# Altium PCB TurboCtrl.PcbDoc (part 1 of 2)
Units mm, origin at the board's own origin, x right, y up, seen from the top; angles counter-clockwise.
Board outline 40.25 x 40.25 mm, 4 copper layers (Top Layer, GND, SIGNAL, Bottom Layer), stack 1.571 mm thick; 111 components, 99 nets, 426 pads, 163 vias.
Unrouted connection lines stored in the file: 47.
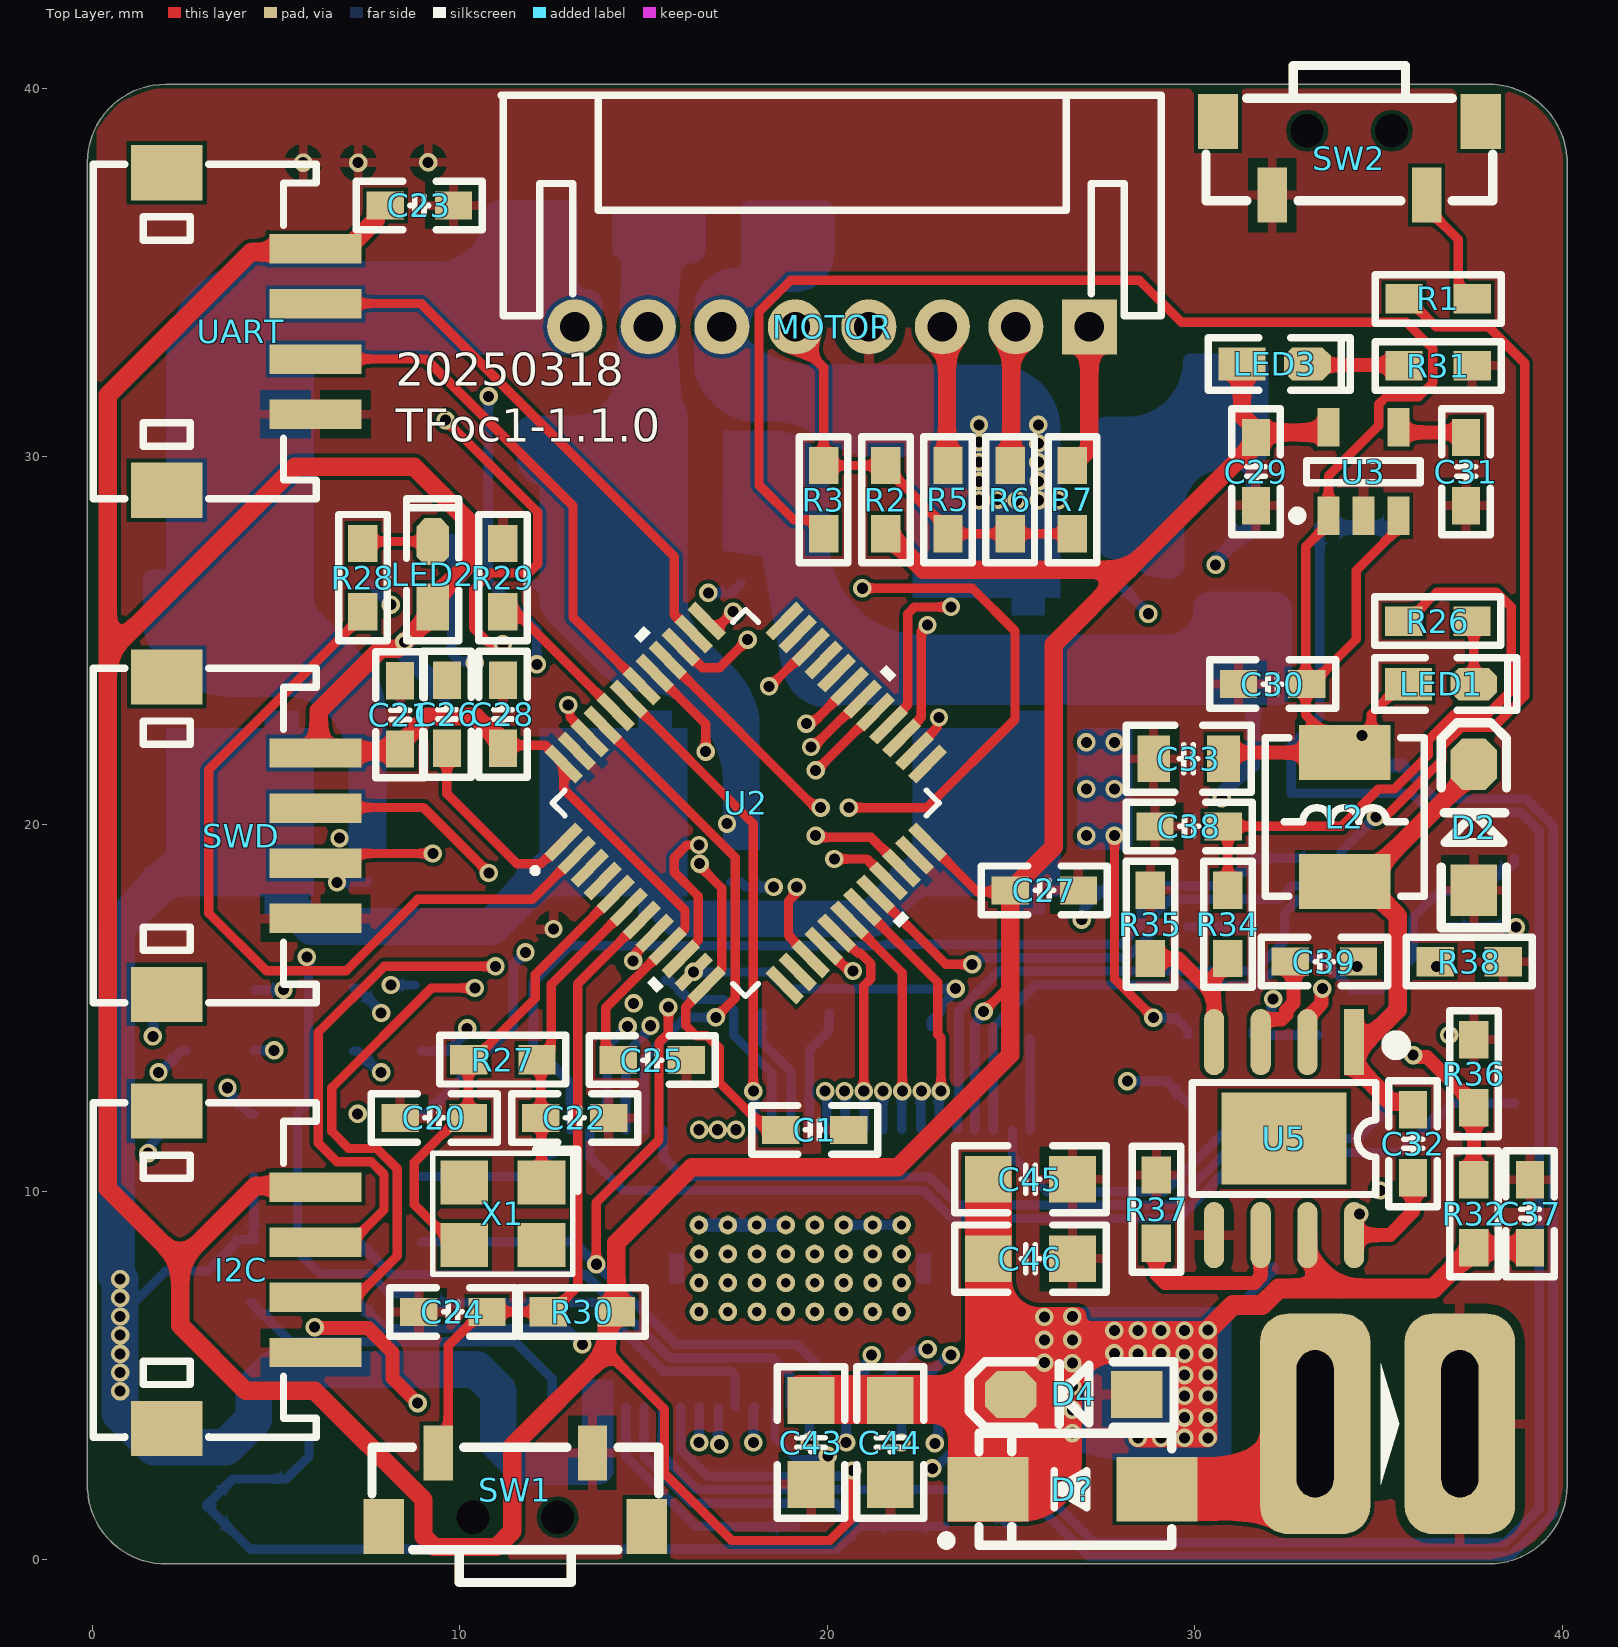
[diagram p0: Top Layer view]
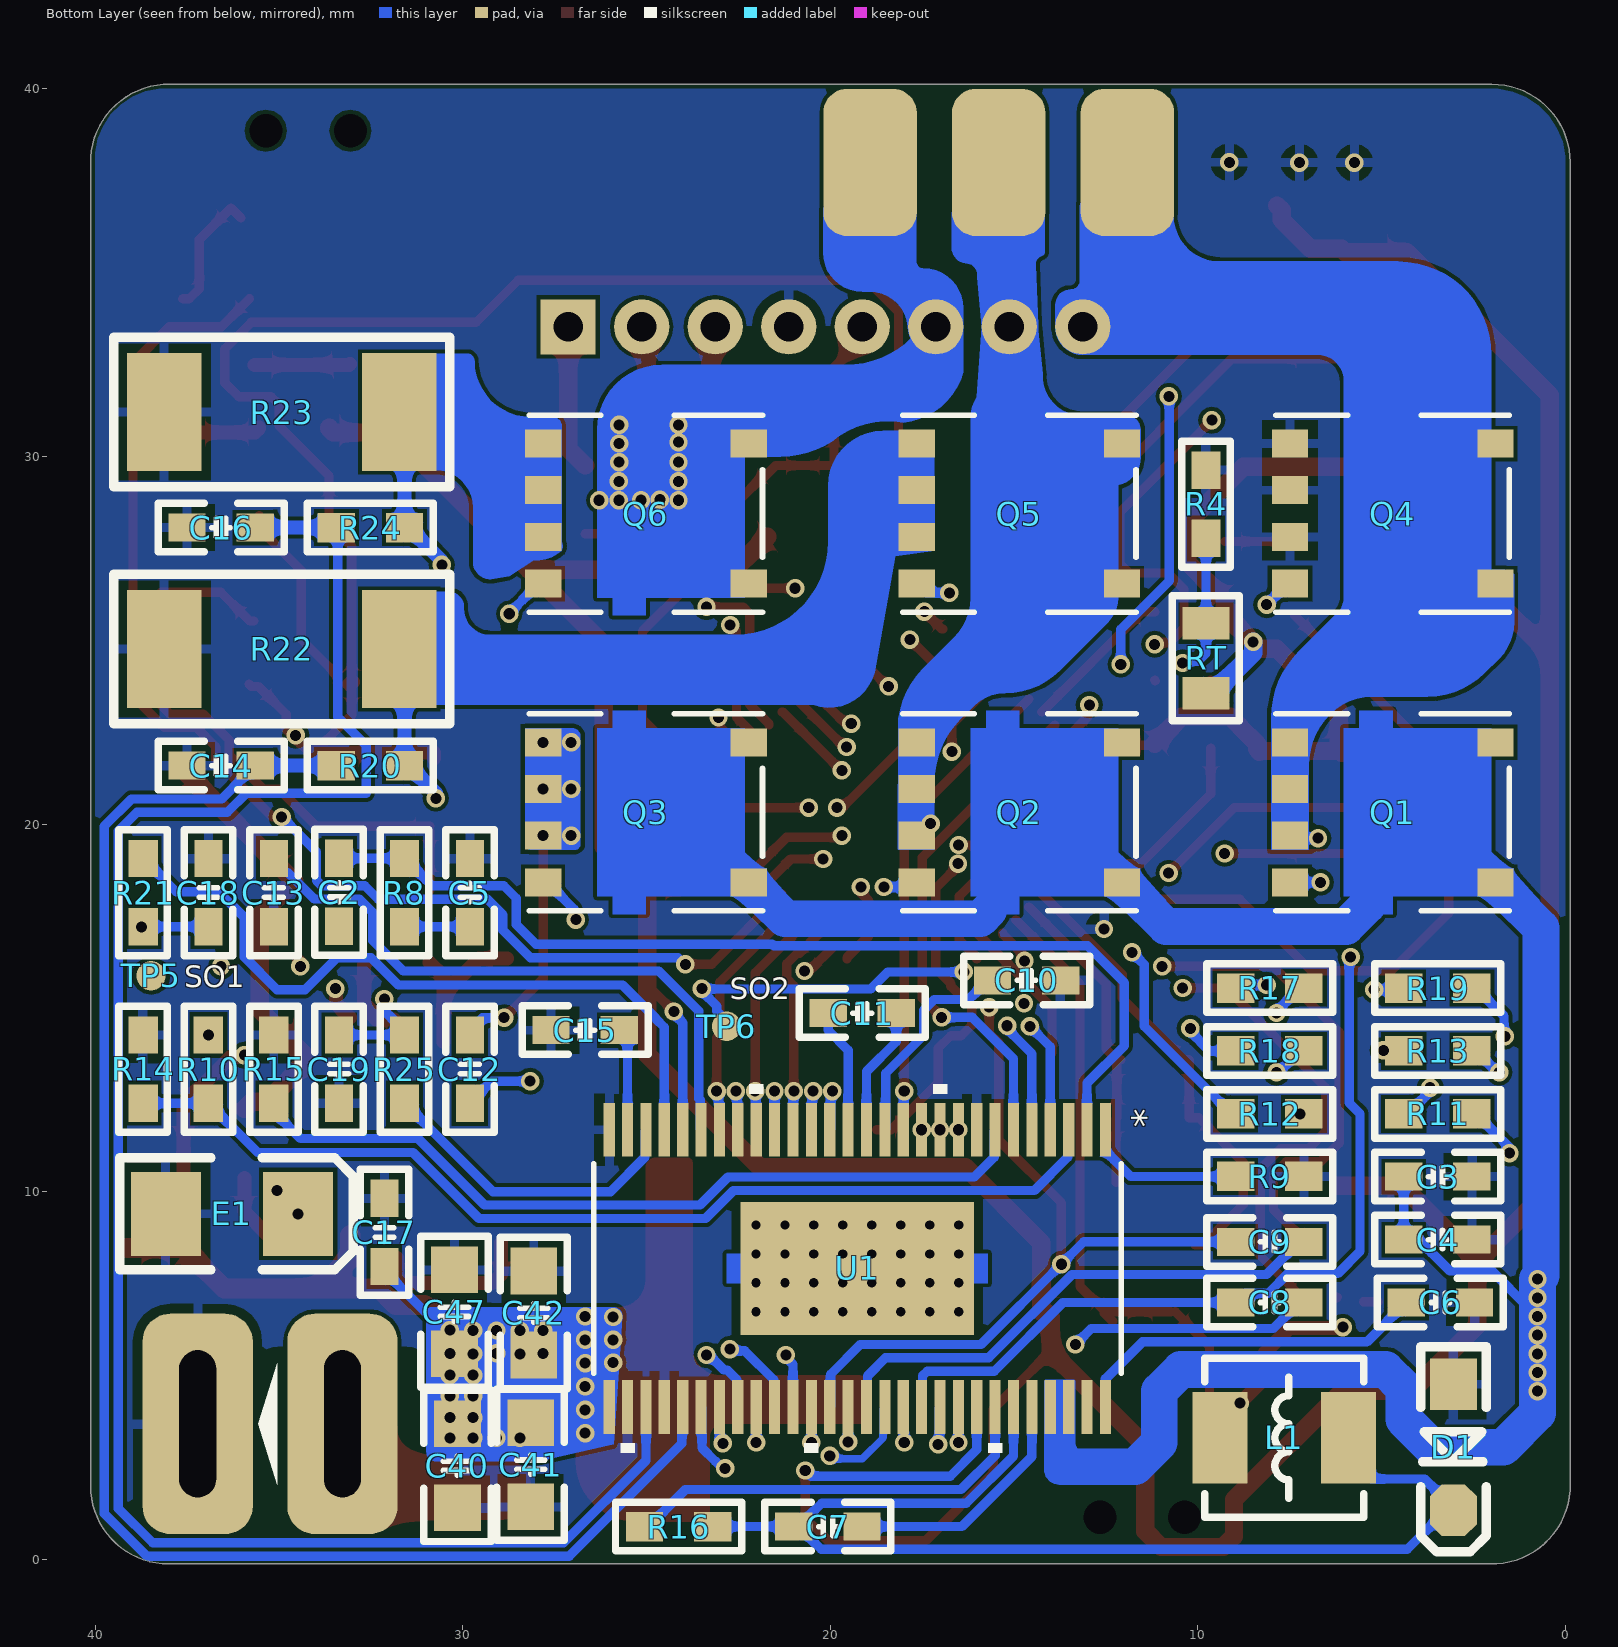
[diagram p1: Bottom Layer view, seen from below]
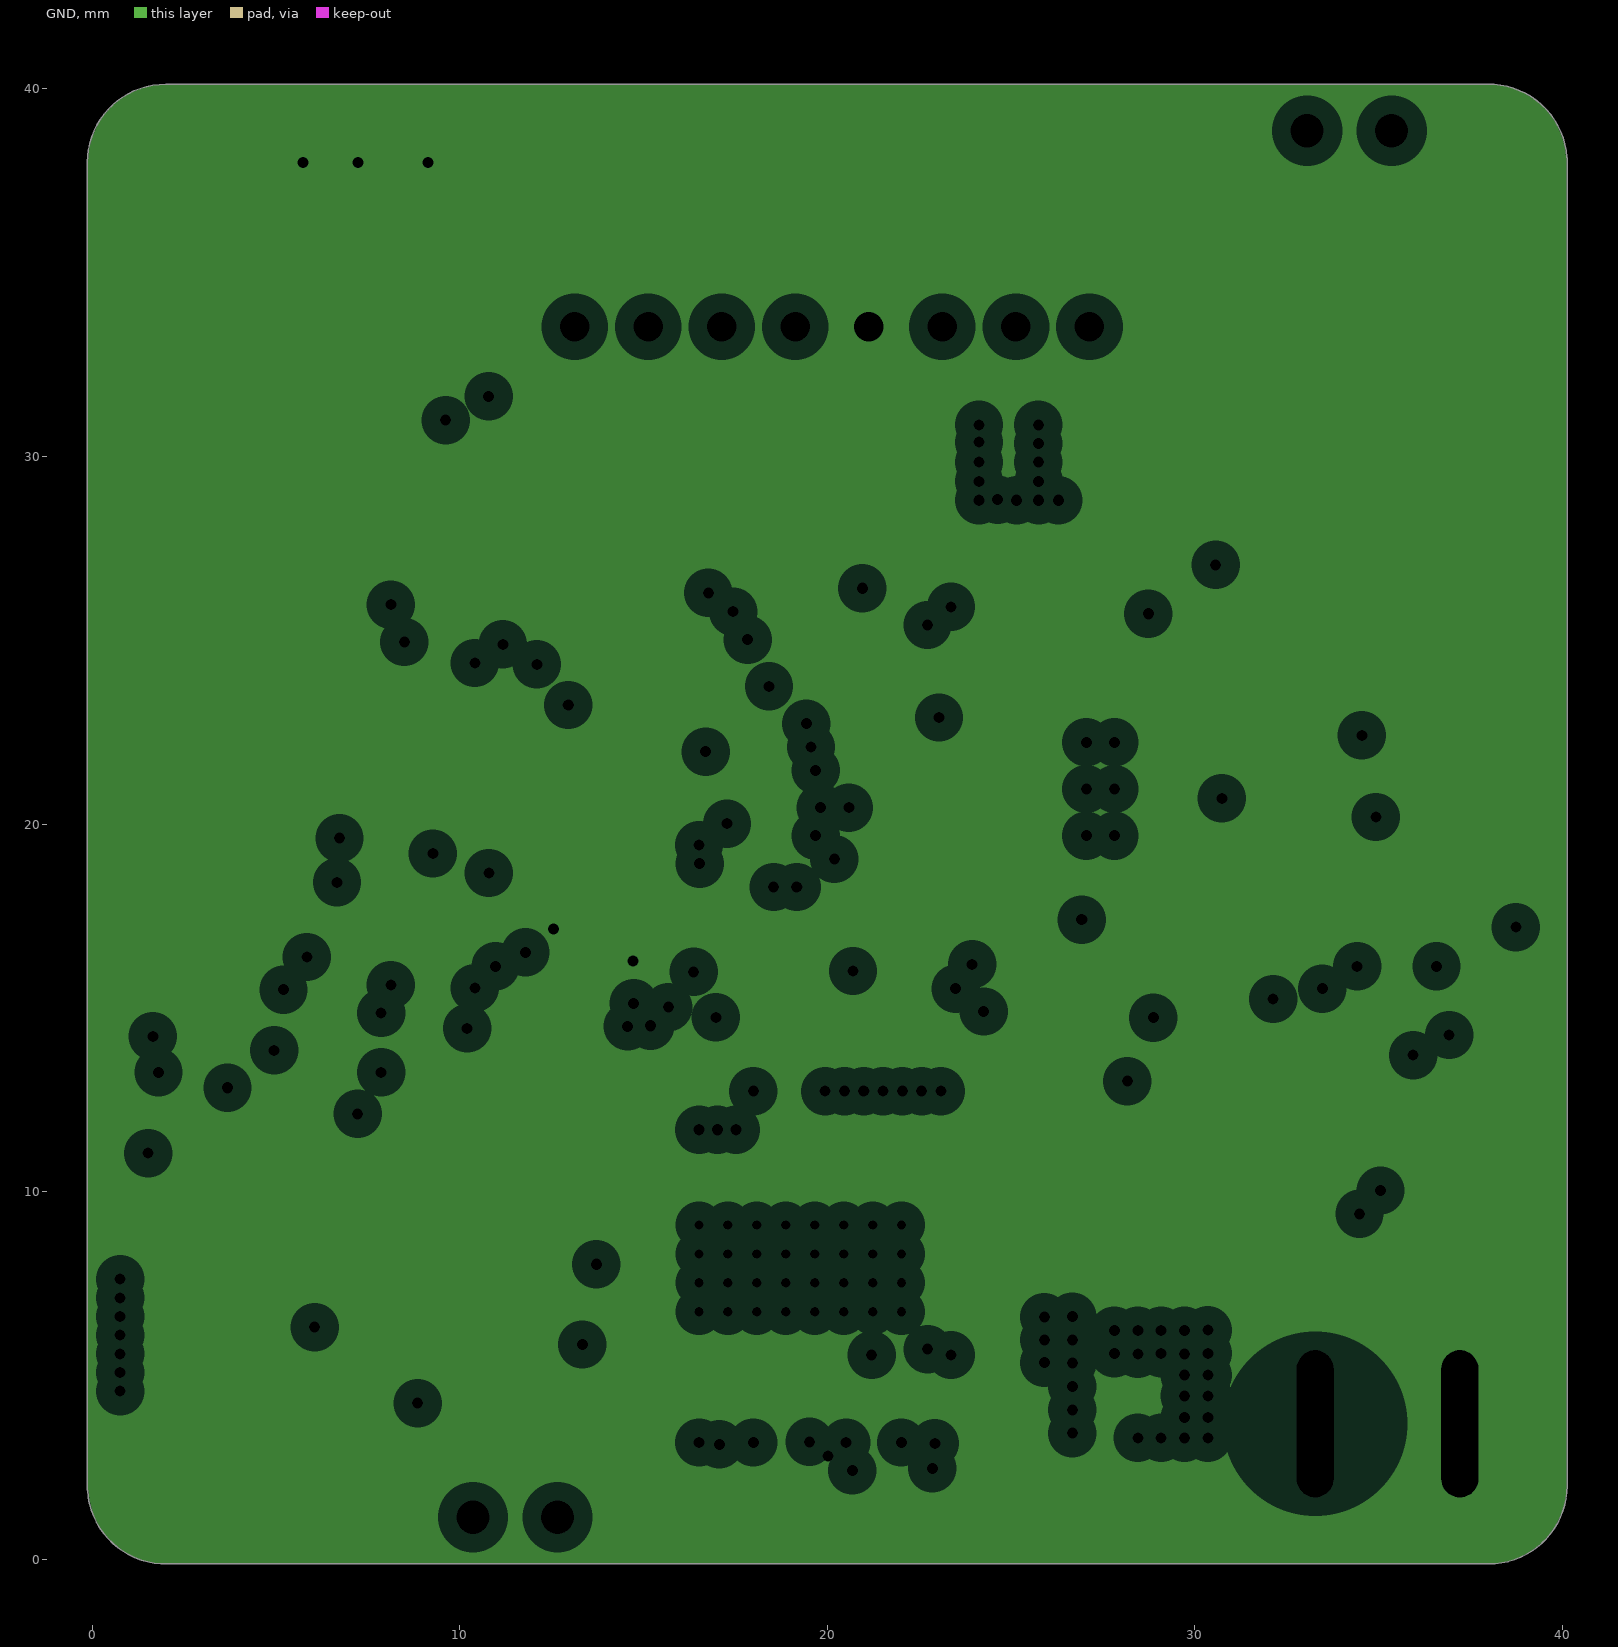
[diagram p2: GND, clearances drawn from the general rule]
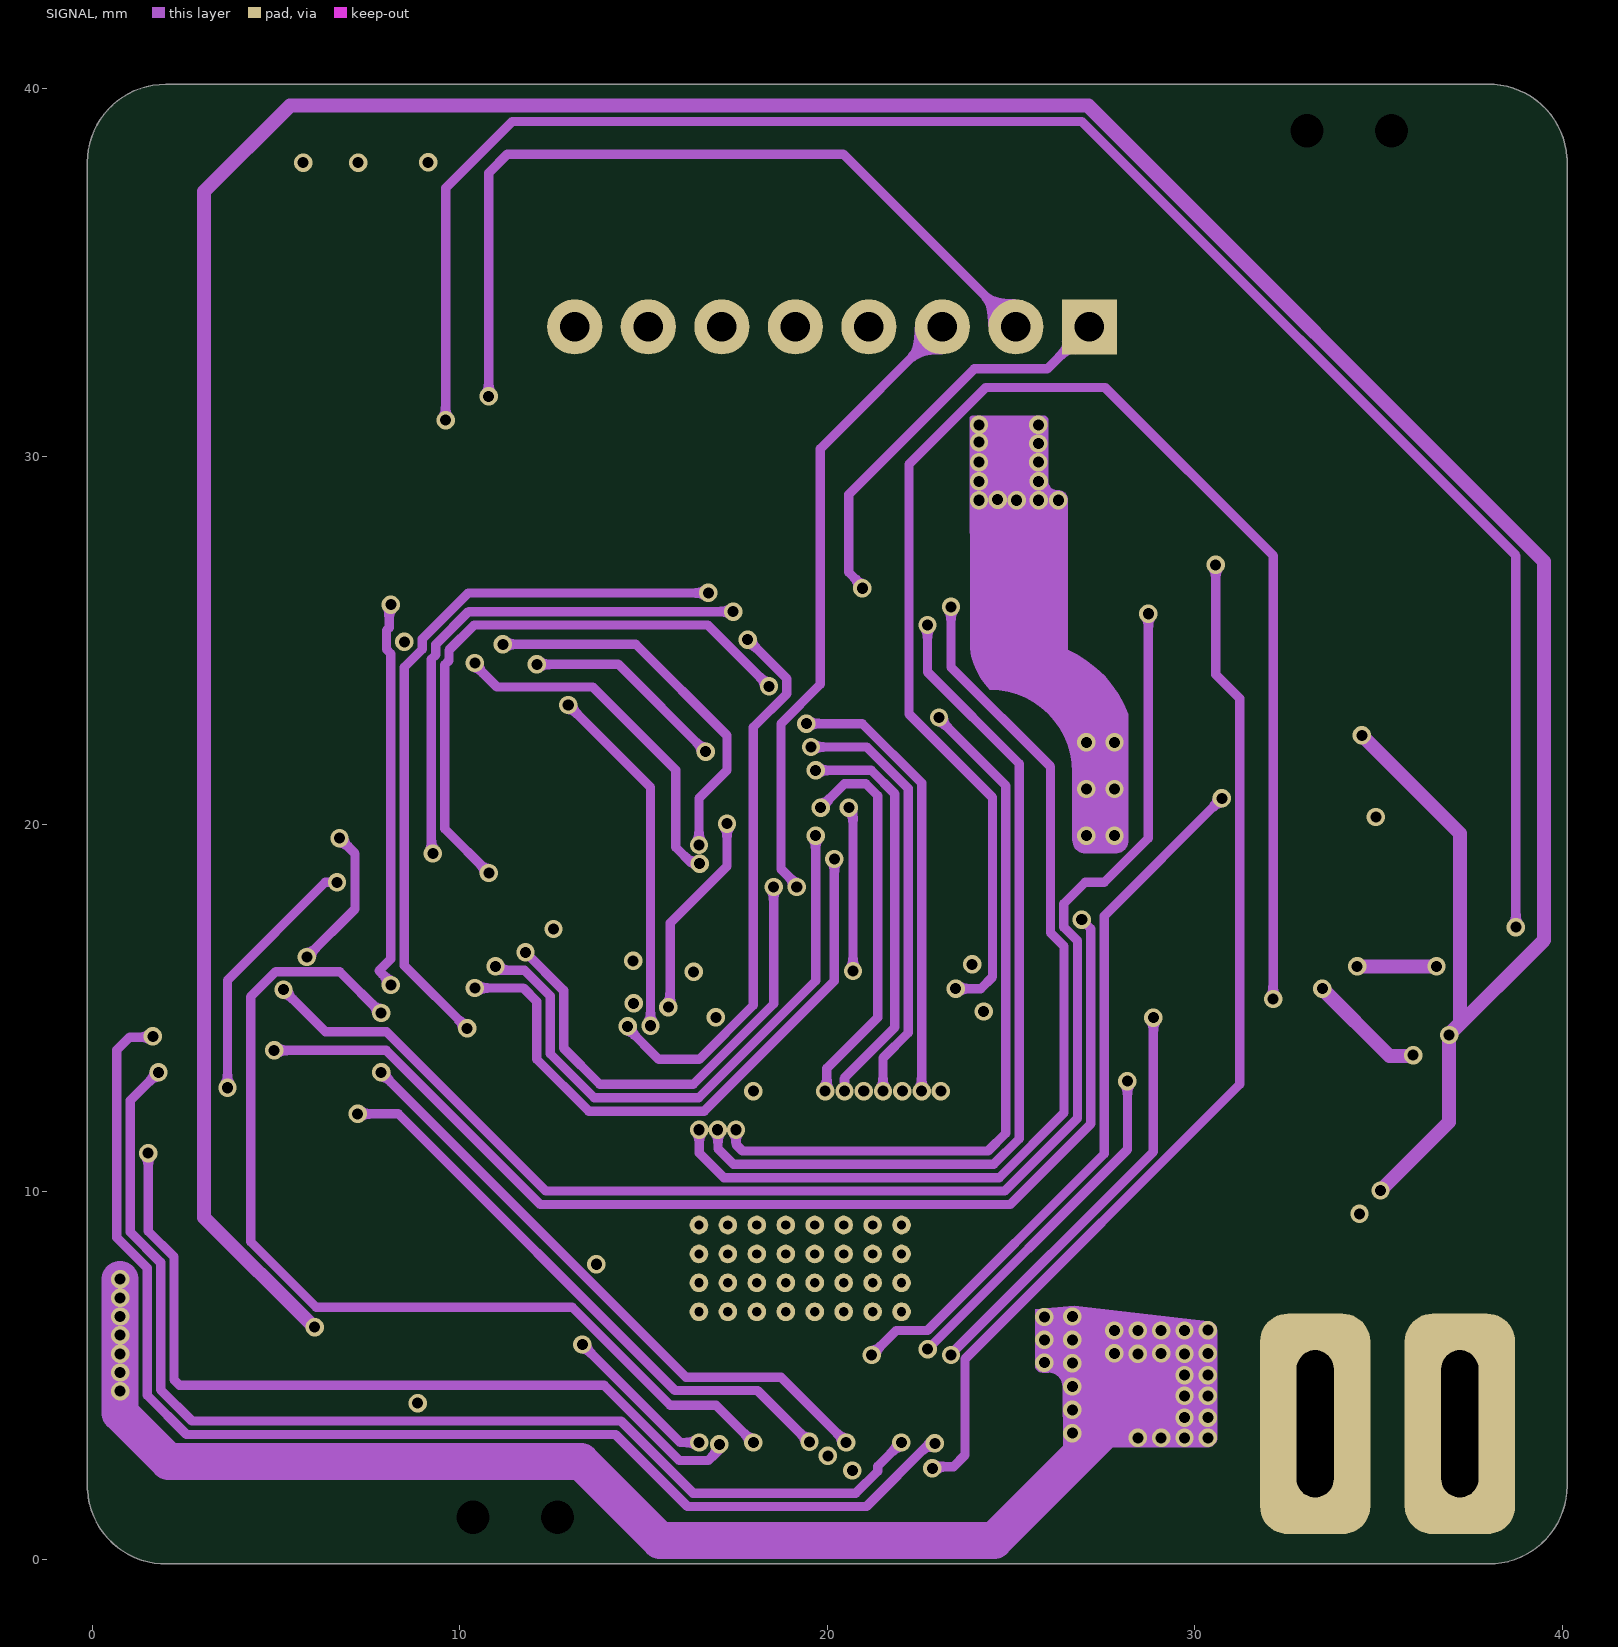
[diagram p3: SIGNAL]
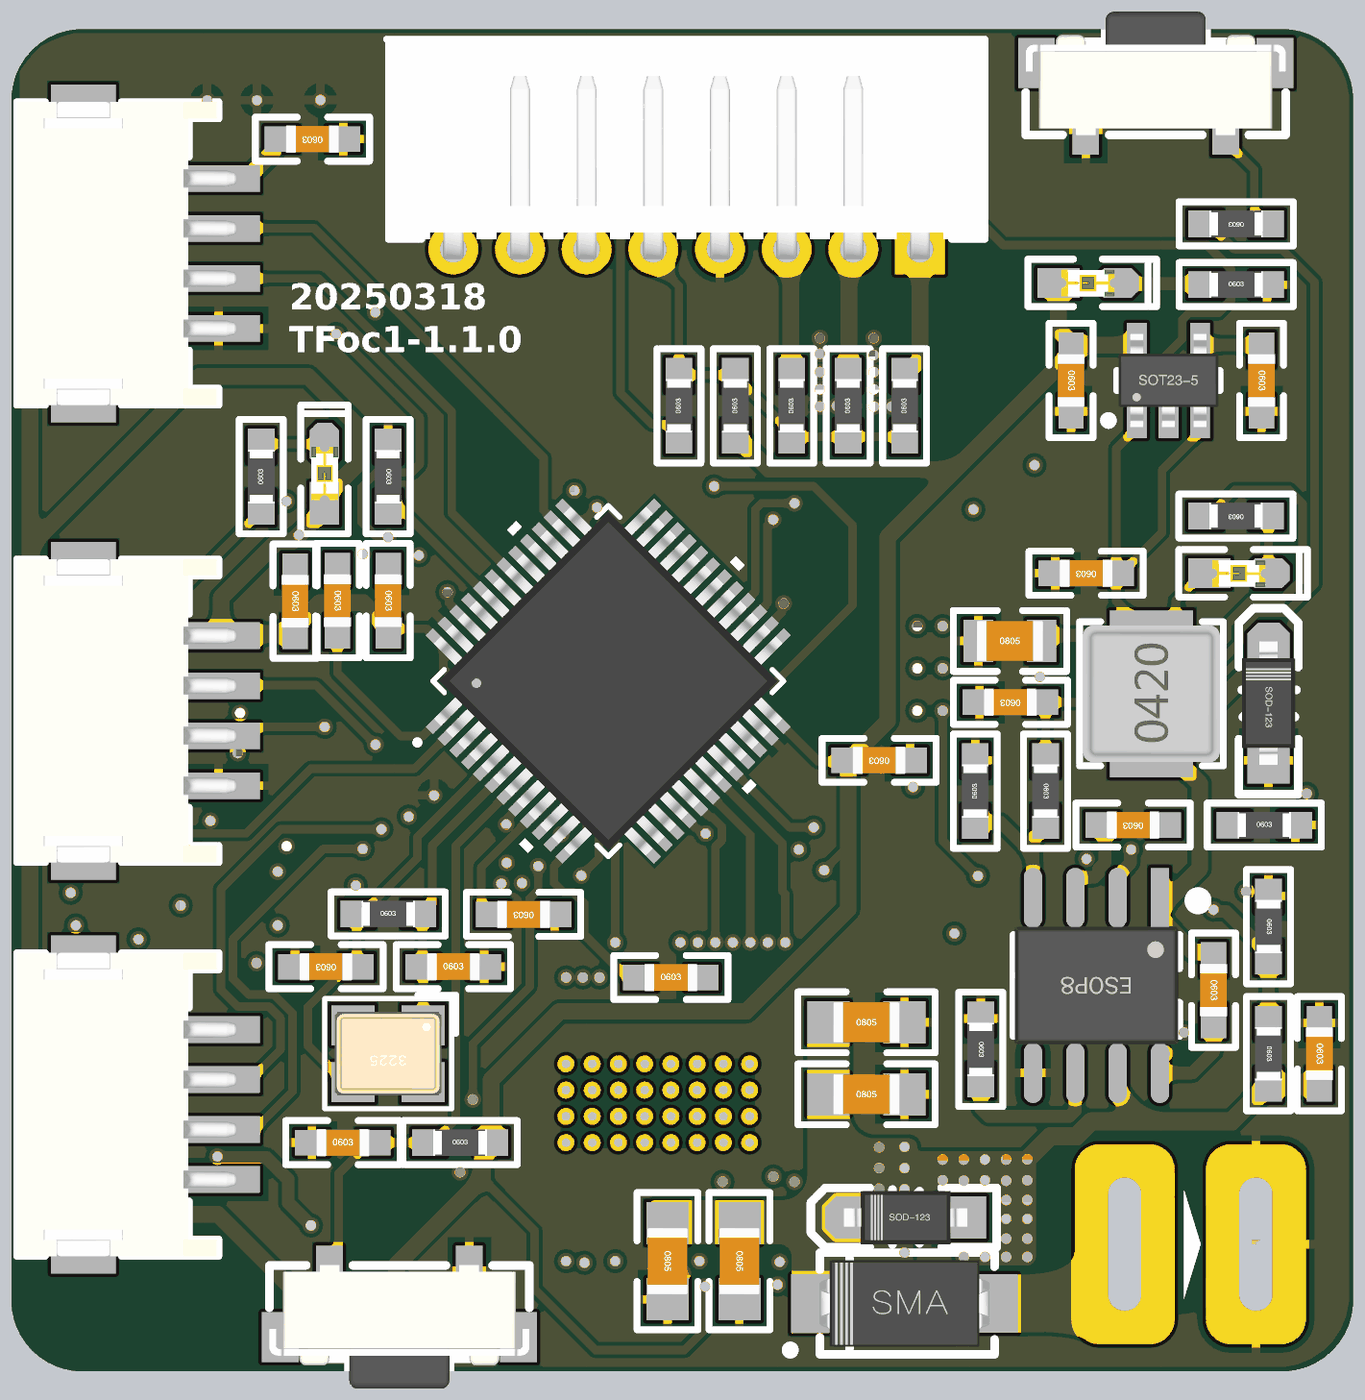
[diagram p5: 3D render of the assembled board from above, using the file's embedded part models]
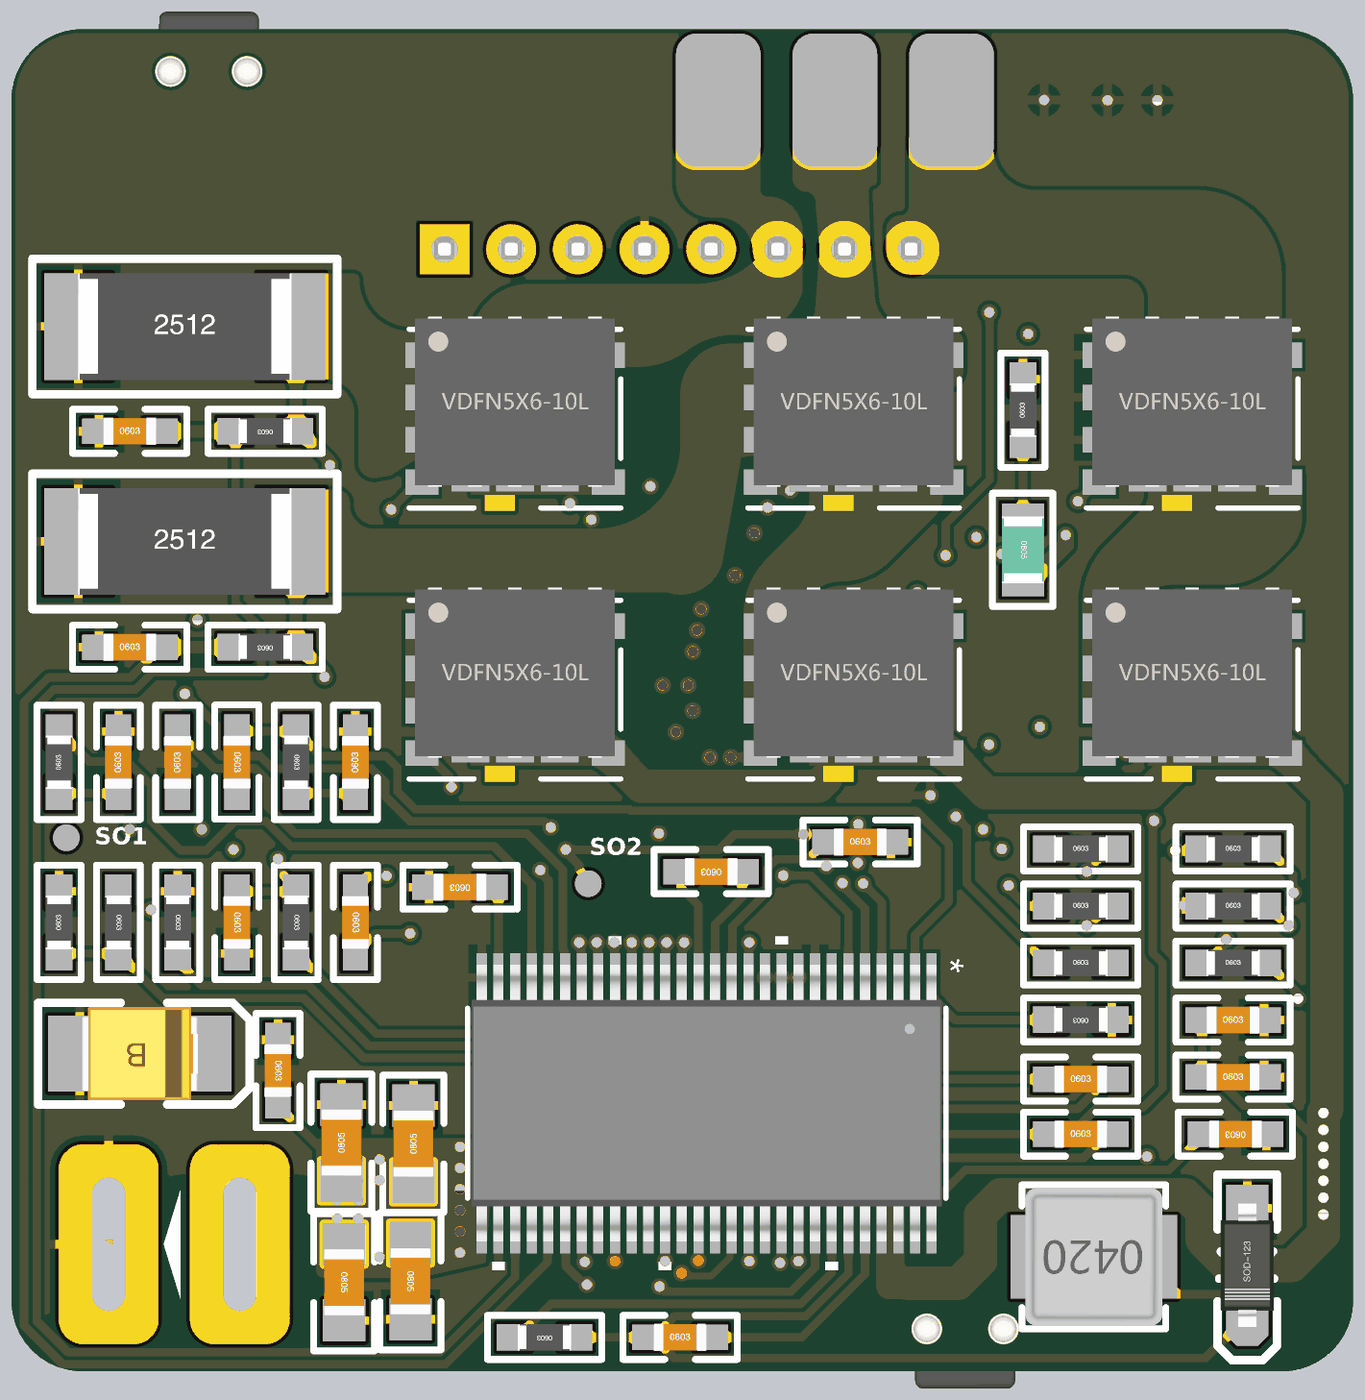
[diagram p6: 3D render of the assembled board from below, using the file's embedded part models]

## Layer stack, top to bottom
Top Solder: solder mask 0.0102, Solder Resist, Dk 3.5
Top Layer: signal copper 0.035
Dielectric 3: prepreg 0.2, PP-JLC7628, Dk 4.5
GND: plane copper 0.018, net GND
Dielectric 1: core 1.065, Core-JLC7628, Dk 4.6
SIGNAL: signal copper 0.018
Dielectric 2: prepreg 0.2, PP-JLC7628, Dk 4.5
Bottom Layer: signal copper 0.035
Bottom Solder: solder mask 0.0102, Solder Resist, Dk 3.5

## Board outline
1.875,-0.124 cw(c2,2) -0.124,1.875 cw(c0,1.905) -0.127,1.905 -0.127,38 cw(c2,38) 2,40.127 cw(c2,40) 2.001,40.127 38.105,40.127 cw(c38.105,40) 38.139,40.123 cw(c38,38) 40.123,38.139 cw(c40,38.105) 40.127,38.105 40.127,2 cw(c38,2) 38,-0.127 1.905,-0.127 cw(c1.905,0)

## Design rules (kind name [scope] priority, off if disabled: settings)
Clearance [All] p1: gap=0.11 ignorepadtopadclearanceinfootprint=TRUE
PlaneClearance [All] p1: clearance=0.508
PlaneConnect [All] p1: planeconnectstyle=Relief reliefexpansion=0.508 reliefentries=4 reliefconductorwidth=0.254 reliefairgap=0.254
PolygonConnect [All] p1: connectstyle=Relief reliefconductorwidth=0.254 reliefentries=4 polygonreliefangle="90 Angle" airgapwidth=0.254
RoutingVias [All] p1: holewidth=0.3 width=0.5 viastyle="Through Hole" minholewidth=0.2 minwidth=0.45 maxholewidth=0.3 maxwidth=0.5
ShortCircuit [All] p1: allowed=TRUE
SolderMaskExpansion [All] p1: expansion=0.102
Width [All] p1: maxlimit=5 minlimit=0.01 preferedwidth=0.254
27 further rules are at their usual default settings.

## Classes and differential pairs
component class U_POWER: C29 C30 C31 C32 C33 C37 C38 C39 D2 D4 D? L2 LED1 LED3 R26 R31 R32 R34 R35 R36 R37 R38 U3 U5
component class MAIN: I2C
component class U_STM32F031C6T6: C20 C21 C22 C23 C24 C25 C26 C27 C28 LED2 R1 R27 R28 R29 R30 SW1 SW2 SWD U2 UART X1
component class U_MOTOR: C1 C2 C3 C4 C5 C6 C7 C8 C9 C10 C11 C12 C13 C14 C15 C16 C17 C18 C19 C40 C41 C42 C43 C44 C45 C46 C47 D1 E1 L1 MOTOR Q1 Q2 Q3 Q4 Q5 Q6 R2 R3 R4 R5 R6 R7 R8 R9 R10 R11 R12 R13 R14 R15 R16 R17 R18 R19 R20 R21 R22 R23 R24 R25 RT TP5 TP6 U1

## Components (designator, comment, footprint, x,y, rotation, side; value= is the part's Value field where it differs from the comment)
C1 "2.2uF" C0603_M 19.66,11.684 r0 top
C2 "82pF" C0603_M 33.363,18.143 r270 bottom
C3 "68nF" C0603_M 3.472,10.407 r180 bottom
C4 "47nF" C0603_M 3.472,8.696 r180 bottom
C5 "270pF" C0603_M 29.807,18.138 r90 bottom
C6 "0.015uF" C0603_M 3.403,6.985 r0 bottom
C7 "100nF" C0603_M 20.066,0.889 r180 bottom
C8 "100nF" C0603_M 8.044,6.985 r180 bottom
C9 "100nF" C0603_M 8.044,8.636 r180 bottom
C10 "2.2uF" C0603_M 14.662,15.748 r180 bottom
C11 "22nF" C0603_M 19.132,14.859 r0 bottom
C12 "100nF" C0603_M 29.807,13.335 r270 bottom
C13 "2.2uF" C0603_M 35.141,18.138 r90 bottom
C14 "2200pF" C0603_M 36.576,21.59 r180 bottom
C15 "2.2uF" C0603_M 26.67,14.393 r0 bottom
C16 "2200pF" C0603_M 36.576,28.067 r180 bottom
C17 "68nF" C0603_M 32.131,8.89 r270 bottom
C18 "2.2uF" C0603_M 36.919,18.138 r90 bottom
C19 "2.2uF" C0603_M 33.363,13.335 r270 bottom
C20 "20p" C0603_M 9.309,12.008 r180 top
C21 "104" C0603_M 8.382,22.971 r270 top
C22 "20p" C0603_M 13.132,12.008 r0 top
C23 "104" C0603_M 8.903,36.83 r180 top
C24 "105" C0603_M 9.817,6.731 r0 top
C25 "104" C0603_M 15.24,13.576 r180 top
C26 "104" C0603_M 9.652,22.987 r270 top
C27 "104" C0603_M 25.908,18.199 r180 top
C28 "104" C0603_M 11.176,22.987 r270 top
C29 "1uF" C0603_M 31.666,29.591 r270 top
C30 "1nF" C0603_M 32.117,23.808 r180 top
C31 "22nF" C0603_M 37.381,29.591 r270 top
C32 "100nF" C0603_M 35.941,11.303 r270 top
C33 "104" C0805_L 29.83,21.779 r0 top
C37 "100nF" C0603_M 39.116,9.398 r270 top
C38 "100nF" C0603_M 29.845,19.939 r180 top
C39 "100nF" C0603_M 33.528,16.256 r180 top
C40 "100uF" C0805_M 30.145,2.54 r270 bottom
C41 "100uF" C0805_M 28.154,2.573 r270 bottom
C42 "100uF" C0805_M 28.067,6.699 r90 bottom
C43 "100uF" C0805_M 19.558,3.175 r270 top
C44 "100uF" C0805_M 21.717,3.175 r270 top
C45 "100uF" C0805_M 25.527,10.338 r0 top
C46 "100uF" C0805_M 25.527,8.179 r0 top
C47 "100uF" C0805_M 30.226,6.731 r90 bottom
D1 "1N4007" SOD-123 3.048,3.048 r270 bottom
D2 "1N4007" SOD-123 37.592,19.914 r90 top
D4 "TVS" SOD-123 26.704,4.483 r180 top
D? "TVS" SMA 26.67,1.905 r180 top
E1 "68uF" C_3528 36.279,9.398 r0 bottom
I2C "HDR-1X4" ZH1.5-WS-4P 2.032,7.874 r270 top
L1 "22uH" L-SMD-0420 7.651,3.304 r0 bottom
L2 "10uH" L-SMD-0420 34.079,20.193 r90 top
LED1 "蓝色" LED0603_B 36.703,23.802 r0 top
LED2 "蓝色" LED0603_B 9.271,26.797 r90 top
LED3 "红色" LED0603_R 32.174,32.512 r0 top
MOTOR "HDR-1X8" PH2.0-W-8P 20.132,33.528 r180 top
Q1 "MOSFET-N" DFN5_5X6_ONS 4.699,20.32 r180 bottom
Q2 "MOSFET-N" DFN5_5X6_ONS 14.859,20.32 r180 bottom
Q3 "MOSFET-N" DFN5_5X6_ONS 25.019,20.32 r180 bottom
Q4 "MOSFET-N" DFN5_5X6_ONS 4.699,28.448 r180 bottom
Q5 "MOSFET-N" DFN5_5X6_ONS 14.859,28.448 r180 bottom
Q6 "MOSFET-N" DFN5_5X6_ONS 25.019,28.448 r180 bottom
R1 "10K" R0603_M 36.619,34.29 r180 top
R2 "0R" R0603_M 21.593,28.829 r90 top
R3 "0R" R0603_M 19.901,28.829 r90 top
R4 "3.3K" R0603_M 9.779,28.702 r90 bottom
R5 "120R" R0603_M 23.286,28.829 r90 top
R6 "120R" R0603_M 24.978,28.829 r90 top
R7 "120R" R0603_M 26.67,28.829 r90 top
R8 "47K" R0603_M 31.585,18.138 r270 bottom
R9 "220k" R0603_M 8.044,10.414 r0 bottom
R10 "18K" R0603_M 36.919,13.335 r270 bottom
R11 "2.2R" R0603_M 3.472,12.118 r180 bottom
R12 "2.2R" R0603_M 8.044,12.118 r180 bottom
R13 "2.2R" R0603_M 3.472,13.828 r180 bottom
R14 "3.3K" R0603_M 38.697,13.335 r90 bottom
R15 "18K" R0603_M 35.141,13.335 r270 bottom
R16 "0R" R0603_M 24.13,0.889 r0 bottom
R17 "2.2R" R0603_M 8.044,15.539 r180 bottom
R18 "2.2R" R0603_M 8.044,13.828 r180 bottom
R19 "2.2R" R0603_M 3.472,15.539 r180 bottom
R20 "120R" R0603_M 32.512,21.59 r0 bottom
R21 "22R" R0603_M 38.697,18.138 r90 bottom
R22 "500uOhm" R2512_M 34.925,24.765 r180 bottom
R23 "500uOhm" R2512_M 34.925,31.211 r180 bottom
R24 "120R" R0603_M 32.512,28.067 r0 bottom
R25 "22R" R0603_M 31.585,13.335 r270 bottom
R26 "1K" R0603_M 36.614,25.524 r180 top
R27 "1M" R0603_M 11.176,13.589 r0 top
R28 "10K" R0603_M 7.366,26.708 r90 top
R29 "10K" R0603_M 11.176,26.708 r270 top
R30 "10K" R0603_M 13.335,6.731 r0 top
R31 "1K" R0603_M 36.619,32.468 r0 top
R32 "1K" R0603_M 37.592,9.398 r270 top
R34 "1K" R0603_M 30.899,17.272 r270 top
R35 "1K" R0603_M 28.791,17.272 r90 top
R36 "1K" R0603_M 37.592,13.208 r270 top
R37 "200K" R0603_M 28.956,9.525 r270 top
R38 "1K" R0603_M 37.465,16.256 r0 top
RT "10K" R0805-HP_L 9.779,24.511 r270 bottom
SW1 "3x6x5" "SW 3*6*4.3-S-W" 11.512,1.143 r0 top
SW2 "3x6x5" "SW 3*6*4.3-S-W" 34.206,38.862 r180 top
SWD "HDR-1X4" ZH1.5-WS-4P 2.032,19.685 r270 top
TP5 "SO1" "TEST 0.8" 38.481,15.875 r90 bottom
TP6 "SO2" "TEST 0.8" 22.821,14.498 r90 bottom
U1 "DRV8301DCA" DRV8301DCA 19.266,7.912 r270 bottom
U2 "STM32F031C6T6" LQFP48-7x7mm 17.78,20.574 r45 top
U3 "RT9193-30GB" SOT-23-5 34.587,29.591 r90 top
U5 "MP1584EN" ESOP8_N 32.428,11.445 r270 top
UART "HDR-1X4" ZH1.5-WS-4P 2.032,33.401 r270 top
X1 "8M" XTAL-3225-4P 11.176,9.398 r180 top

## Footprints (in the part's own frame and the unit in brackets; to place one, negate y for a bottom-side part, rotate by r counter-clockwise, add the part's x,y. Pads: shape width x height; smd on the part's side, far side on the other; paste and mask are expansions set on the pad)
C0603_M [mil]
  rect 40x30 smd: 1(-36.5,0) 2(36.5,0)
  silkscreen extent -68,-26 68,26, body extent -31,-16 31,16, height 33
C0805_L [mil]
  rect 35x50 smd: 1(-37.4,0) 2(37.4,0)
  silkscreen extent -67,-36 67,36, body extent -39,-24 39,24, height 22
C0805_M [mil]
  rect 50x50 smd: 1(-45,0) 2(45,0)
  silkscreen extent -81,-36 81,36, body extent -39,-24 39,24, height 22
C_3528 [mil]
  rect 75x90 smd: 1(-70.87,-0.01) 2(70.86,-0.01)
  silkscreen extent -130,-60 120,60, body extent -69,-55 69,55, height 76
DFN5_5X6_ONS [mil]
  rect 39x30 smd paste+0 mask+0: D(110.04,-75) D(110.04,75) G(-110.04,-75) S(-110.04,-25) S(-110.04,25) S(-110.04,75)
  Top Layer region: 0,-90 -35.63,-90 -35.63,-90 -35.63,-90 -35.63,-109 0,-109 0,-90 0,-90
  Top Layer region: 0,90 -35.63,90 -35.63,90 -35.63,90 -35.63,109 0,109 0,90 0,90
  Top Layer region: 105.77,90 -52.23,90 -52.23,-90 105.77,-90
  silkscreen extent -125,-106 125,106, body extent -118,-80 118,120, height 42
DRV8301DCA [mil]
  rect 57.56x12 smd paste+0 mask+0: 1(-148.5,265.75) 2(-148.5,246.06) 3(-148.5,226.38) 4(-148.5,206.69) 5(-148.5,187.01) 6(-148.5,167.32) 7(-148.5,147.64) 8(-148.5,127.95) 9(-148.5,108.27) 10(-148.5,88.58) 11(-148.5,68.9) 12(-148.5,49.21) 13(-148.5,29.53) 14(-148.5,9.84) 15(-148.5,-9.84) 16(-148.5,-29.53) 17(-148.5,-49.21) 18(-148.5,-68.9) 19(-148.5,-88.58) 20(-148.5,-108.27) 21(-148.5,-127.95) 22(-148.5,-147.64) 23(-148.5,-167.32) 24(-148.5,-187.01) 25(-148.5,-206.69) 26(-148.5,-226.38) 27(-148.5,-246.06) 28(-148.5,-265.75) 29(148.5,-265.75) 30(148.5,-246.06) 31(148.5,-226.38) 32(148.5,-206.69) 33(148.5,-187.01) 34(148.5,-167.32) 35(148.5,-147.64) 36(148.5,-127.95) 37(148.5,-108.27) 38(148.5,-88.58) 39(148.5,-68.9) 40(148.5,-49.21) 41(148.5,-29.53) 42(148.5,-9.84) 43(148.5,9.84) 44(148.5,29.53) 45(148.5,49.21) 46(148.5,68.9) 47(148.5,88.58) 48(148.5,108.27) 49(148.5,127.95) 50(148.5,147.64) 51(148.5,167.32) 52(148.5,187.01) 53(148.5,206.69) 54(148.5,226.38) 55(148.5,246.06) 56(148.5,265.75)
  rect 142.13x250 smd paste-124.5 mask-124.5: 57(0,0)
  round 20 hole 10: V(-46.5,-108.5) V(-46.5,-77.5) V(-46.5,-46.5) V(-46.5,-15.5) V(-46.5,15.5) V(-46.5,46.5) V(-46.5,77.5) V(-46.5,108.5) V(-15.5,-108.5) V(-15.5,-77.5) V(-15.5,-46.5) V(-15.5,-15.5) V(-15.5,15.5) V(-15.5,46.5) V(-15.5,77.5) V(-15.5,108.5) V(15.5,-108.5) V(15.5,-77.5) V(15.5,-46.5) V(15.5,-15.5) V(15.5,15.5) V(15.5,46.5) V(15.5,77.5) V(15.5,108.5) V(46.5,-108.5) V(46.5,-77.5) V(46.5,-46.5) V(46.5,-15.5) V(46.5,15.5) V(46.5,46.5) V(46.5,77.5) V(46.5,108.5)
  Top Layer region: 15.75,-125 -15.75,-125 -15.75,-125 -15.75,-125 -15.75,-139.96 15.75,-139.96 15.75,-125 15.75,-125
  Top Layer region: 15.75,125 -15.75,125 -15.75,125 -15.75,125 -15.75,139.96 15.75,139.96 15.75,125 15.75,125
  silkscreen extent -197,-282 197,282, body extent -164,-277 164,277, height 67
ESOP8_N [mm] "5*6*1.8mm（长宽高）封装库来自淘宝卖家 ID：黄晶宝石"
  rect 1.8x0.55 smd: 1(-2.625,1.905)
  oval 1.8x0.55 smd: 2(-2.625,0.635) 3(-2.625,-0.635) 4(-2.625,-1.905) 5(2.625,-1.905) 6(2.625,-0.635) 7(2.625,0.635) 8(2.625,1.905)
  rect 2.5x3.4 smd paste-2: 9(0,0)
  rect 0.9x0.7 on Top Paste: 10(-0.625,1.1) 10(-0.625,0) 10(-0.625,-1.1) 11(0.65,1.1) 11(0.65,0) 11(0.65,-1.1)
  silkscreen extent -2.69,-2.5 1.52,3.2, body extent -3,-2.5 3,2.5
L-SMD-0420 [mm]
  rect 1.5x2.5 smd: 1(-1.75,0) 2(1.75,0)
  silkscreen extent -2.16,-2.16 2.16,2.16, body extent -2.25,-2.05 2.25,2.05
LED0603_B [mil] "蓝色0603LED"
  rect 50x35 smd: 1(-35,0.26)
  oct 50x35 smd: 2(35,0.26)
  silkscreen extent -71,-28 81,28, body extent -32,-16 31,16, height 18
LED0603_R [mil] "红色0603LED"
  rect 50x35 smd: 1(-35,0.26)
  oct 50x35 smd: 2(35,0.26)
  silkscreen extent -71,-28 81,28, body extent -32,-16 31,16, height 18
LQFP48-7x7mm [mm]
  rect 1.194x0.305 smd paste+0 mask+0: 1(-4.25,2.75) 2(-4.25,2.25) 3(-4.25,1.75) 4(-4.25,1.25) 5(-4.25,0.75) 6(-4.25,0.25) 7(-4.25,-0.25) 8(-4.25,-0.75) 9(-4.25,-1.25) 10(-4.25,-1.75) 11(-4.25,-2.25) 12(-4.25,-2.75) 25(4.25,-2.75) 26(4.25,-2.25) 27(4.25,-1.75) 28(4.25,-1.25) 29(4.25,-0.75) 30(4.25,-0.25) 31(4.25,0.25) 32(4.25,0.75) 33(4.25,1.25) 34(4.25,1.75) 35(4.25,2.25) 36(4.25,2.75)
  rect 0.305x1.194 smd paste+0 mask+0: 13(-2.75,-4.25) 14(-2.25,-4.25) 15(-1.75,-4.25) 16(-1.25,-4.25) 17(-0.75,-4.25) 18(-0.25,-4.25) 19(0.25,-4.25) 20(0.75,-4.25) 21(1.25,-4.25) 22(1.75,-4.25) 23(2.25,-4.25) 24(2.75,-4.25) 37(2.75,4.25) 38(2.25,4.25) 39(1.75,4.25) 40(1.25,4.25) 41(0.75,4.25) 42(0.25,4.25) 43(-0.25,4.25) 44(-0.75,4.25) 45(-1.25,4.25) 46(-1.75,4.25) 47(-2.25,4.25) 48(-2.75,4.25)
  silkscreen extent -5.43,-5.35 5.35,5.35, body extent -4.5,-4.5 4.5,4.5, height 1.6
PH2.0-W-8P [mm] "长：17.9mm，宽：6mm，高：4.7mm     淘宝ID:黄晶宝石"
  rect 1.5x1.5 hole 0.8: 1(-7,0)
  round 1.5 hole 0.8: 2(-5,0) 3(-3,0) 4(-1,0) 5(1,0) 6(3,0) 7(5,0) 8(7,0)
  silkscreen extent -8.95,-6.3 9,-0.3, body extent -8.95,-6.3 8.95,0.3, height 4.75
R0603_M [mil]
  rect 40x31.5 smd: 1(-36.5,0) 2(36.5,0)
  silkscreen extent -68,-26 68,26, body extent -31,-16 32,16, height 16
R0805-HP_L [mm]
  rect 0.889x1.27 smd: 1(-0.95,0) 2(0.95,0)
  silkscreen extent -1.7,-0.91 1.7,0.9, body extent -1,-0.62 1,0.63, height 0.5
R2512_M [mm]
  rect 2.032x3.2 smd: 1(-3.2,0) 2(3.2,0)
  silkscreen extent -4.57,-2.03 4.57,2.03, body extent -3.2,-1.6 3.2,1.6, height 0.55
SMA [mm] "4.5x2.6*2.2mm（长宽高，不包括引脚）联系卖家 免费查找封装"
  rect 2.2x1.75 smd: 1(-2.3,0) 2(2.3,0)
  silkscreen extent -2.7,-1.52 3.56,1.52, body extent -2.55,-1.3 2.55,1.3, height 2.15
SOD-123 [mil] "2.7x1.6X1.1mm（长宽高，不包括引脚） 淘宝ID:黄晶宝?"
  rect 55x50 smd: 1(-67.5,0)
  oct 55x50 smd: 2(67.5,0)
  silkscreen extent -108,-35 112,35, body extent -73,-31 73,31, height 50
SOT-23-5 [mm] "SOT23, 5-Leads, Body 2.9x1.6mm, Pitch 0.95mm, IPC Medium Density"
  rect 1.05x0.6 smd: 1(-1.2,0.95) 2(-1.2,0) 3(-1.2,-0.95) 4(1.2,-0.95) 5(1.2,0.95)
  silkscreen extent -1.32,-1.55 0.3,1.92, body extent -1.4,-1.5 1.4,1.5, height 1.15
"SW 3*6*4.3-S-W" [mm] "侧立贴片3*6*4.3"
  rect 1.1x1.5 smd: 0(-3.575,-0.25) 0(3.575,-0.25)
  round 0 hole 0.9: 0(-1.15,0) 0(1.15,0)
  rect 0.8x1.5 smd: 1(2.1,1.75) 2(-2.1,1.75)
  silkscreen extent -3.9,-1.78 3.9,1.91, body extent -3.9,-1.79 3.9,1.91, height 3.51
"TEST 0.8" [mm] "?"
  round 0.8 smd: 1(0,0)
XTAL-3225-4P [mm] "3.2*2.5*0.7mm(长宽高)"
  rect 1.3x1.2 smd: 1(-1.05,-0.85) 2(1.05,-0.85) 3(1.05,0.85) 4(-1.05,0.85)
  silkscreen extent -2.03,-1.75 1.91,1.65, body extent -1.6,-1.25 1.6,1.25, height 0.7
ZH1.5-WS-4P [mm] "长：9.1mm，宽：6.0mm，高：3.7mm淘宝ID:黄晶宝石   店铺网址:https://shop463601444.taobao.com"
  rect 1.5x1.95 smd: 0(-4.318,0) 0(4.318,0)
  rect 0.8x2.5 smd: 1(-2.25,4.05) 2(-0.75,4.05) 3(0.75,4.05) 4(2.25,4.05)
  silkscreen extent -4.55,-2 4.55,4.06, body extent -4.55,-2 4.55,4.6, height 3.75

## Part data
C1 C2 C3 C4 C5 C6 C7 C8 C9 C10 C11 C12 C13 C14 C15 C16 C17 C18 C19 C20 C21 C22 C23 C24 C25 C26 C27 C28 C29 C30 C31 C32 C33 C37 C38 C39 C40 C41 C42 C43 C44 C45 C46 C47: library part C, "贴片"
D1 D2: "整流二极管"
D4 D?: "TVS通用"
E1: library part CT
I2C SWD UART: library part "Header 4", "4P接插件"
L1: library part "L-Molding Choke"
L2: library part "L-Molding Choke", "一体成型电感"
LED1 LED2 LED3: library part LED-SMD, "贴片LED"
MOTOR: library part "Header 8", "8P接插件"
Q1 Q2 Q3 Q4 Q5 Q6: "N-Channel MOSFET", PackageDocument=1995/1996
R1 R2 R3 R4 R5 R6 R7 R8 R9 R10 R11 R12 R13 R14 R15 R16 R17 R18 R19 R20 R21 R22 R23 R24 R25 R26 R27 R28 R29 R30 R31 R32 R34 R35 R36 R37 R38: library part R
RT: library part RT
SW1 SW2: library part "SW 3x6", "3x6轻触开关"
TP5 TP6: library part TEST, "测试点"
U1: "No Description Available", Mfr_Name="Texas Instruments"
U2: "No Description Available", Mfr_Name=STMicroelectronics
U3: "LDO 3.0V/0.3A"
U5: "28V/3A降压稳压器"
X1: library part XTAL-4P, "4脚无源晶振(谐振器）"

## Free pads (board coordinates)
  rrect50% 2.54x4 smd far side: MotorPad_U(11.919,38) MotorPad_V(15.419,38) MotorPad_W(18.919,38)
  rrect50% 3x6 hole 4 slot 1 at 0 deg: ""(33.274,3.683) ""(37.211,3.683)

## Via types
v1: diameter 0.5, hole 0.3, Top Layer to Bottom Layer, tented both sides, 163 vias

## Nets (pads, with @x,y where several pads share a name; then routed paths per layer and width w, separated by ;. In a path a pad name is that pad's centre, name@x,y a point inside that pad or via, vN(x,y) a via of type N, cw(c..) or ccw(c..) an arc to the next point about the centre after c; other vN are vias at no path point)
+3.3V: C21.2 C23.2 C25.2 C27.2 C28.2 C29.1 I2C.1 LED2.1 LED3.1 R2.1 R30.2 RT.2 SWD.1 U1.24 U1.49 U2.9 U2.24 U2.48 U3.5 UART.1 | length 169.8
  Top Layer w0.254: C28.2@11.176,22.06 C28.2@11.176,22.187 ; C28.2@11.262,22.146 12.319,22.146 U2.48@12.83,21.635 12.83,20.952 16.129,17.653 16.129,17.155 U2.9@15.659,16.685 13.97,14.996 C25.2@13.97,13.778 ; 14.004,5.648 15.571,4.081 15.571,2.336 17.399,0.508 20.066,0.508 20.682,1.124 v1(20.682,2.413) ; U2.24@22.73,19.513 24.082,18.161 C27.2@24.943,18.161 ; v1(24.257,14.902) 24.849,15.494
  Top Layer w0.5: UART.1@5.991,35.56 4.318,35.56 0.426,31.668 0.426,24.631 ; SWD.1@6.082,21.935 6.137,21.99 8.327,21.99 C21.2@8.327,21.972 ; UART.1@6.082,35.651 6.932,35.651 7.718,36.437 7.718,36.699 C23.2@7.849,36.83 ; SWD.1@6.167,22.02 6.167,23.081 7.852,24.766 8.306,24.766 v1(8.495,24.956) 8.503,24.956 LED2.1@9.264,25.718 ; I2C.1@6.173,10.16 4.445,10.16 2.396,8.111 ; C21.2@8.382,22.044 8.382,22.171 8.867,22.656 8.867,22.673 9.122,22.928 10.435,22.928 C28.2@11.176,22.187 ; LED2.1@9.07,25.714 LED2.1@9.264,25.908 ; LED2.1@9.264,26.099 10.287,27.121 10.287,28.194 8.763,29.718 5.513,29.718 0.426,24.631 ; R2.1@21.717,27.813 22.606,26.924 28.199,26.924 ; LED3.1@31.285,32.519 31.285,31.115 31.745,30.655 33.527,30.655 33.637,30.764 U3.5@33.637,30.791 ; C29.1@31.666,30.518 31.666,30.391 28.199,26.924 ; 0.426,24.631 0.426,10.082 2.396,8.111 ; 2.396,8.111 2.396,6.367 4.178,4.585 6.054,4.585 9.017,1.622 9.017,0.628 9.312,0.333 11.001,0.333 11.43,0.762 11.43,3.074 14.004,5.648 14.004,6.581 14.154,6.731 R30.2@14.262,6.731 14.262,8.609 16.321,10.668 21.92,10.668 24.981,13.729 C27.2@24.981,18.199 26.162,19.38 26.162,24.887 28.199,26.924
  Bottom Layer w0.254: U1.49@16.016,4.14 16.016,2.983 16.74,2.259 20.528,2.259 v1@20.661,2.392 ; U1.24@24.016,11.684 24.016,14.594 24.257,14.835 v1(24.257,14.902)
  Bottom Layer w0.5: v1(8.495,24.956) 8.495,24.654 RT.2@9.588,23.561
+5.0V: C30.1 C33.2 E1.1 L1.2 L2.2 LED1.1 R3.1 R10.1 U3.1 U3.3 | length 158
  Top Layer w0.254: R3.1@19.901,28.01 19.628,28.283 19.088,28.283 18.145,29.226 18.145,33.937 19.006,34.798 28.491,34.798 29.636,33.653 35.75,33.653 36.471,32.932 36.471,32.004 36.09,31.623 35.209,31.623 35,31.414 35,30.839 33.637,29.476 U3.1@33.637,28.391 ; C30.1@33.044,23.808 33.171,23.808 33.02,23.959 33.02,27.549 U3.1@33.637,28.166 ; C30.1@33.108,23.745 33.02,23.657 33.02,22.971 L2.2@34.048,21.943 ; C30.1@33.425,24.062 34.395,25.031 34.395,26.897 35.537,28.04 U3.3@35.537,28.391 ; L2.2@34.179,21.943 34.802,22.566 34.802,22.987 35.56,23.745 35.75,23.745 LED1.1@35.814,23.808
  Top Layer w0.381: v1(6.054,6.314) 6.167,6.314 6.189,6.291 7.513,6.291 8.174,5.63 8.174,4.93 v1(8.858,4.246) ; C33.2@30.78,21.779 C33.2@30.78,21.943 ; C33.2@30.945,21.943 L2.2@34.048,21.943 ; C30.1@32.992,23.86 C30.1@33.044,23.808
  SIGNAL w0.381: v1@6.045,6.304 3.048,9.301 3.048,37.211 5.38,39.543 27.101,39.543 39.497,27.148 39.497,16.84 v1(36.919,14.262) ; v1(34.544,22.412) 37.211,19.745 37.211,14.586 36.919,14.294 v1(36.919,14.262) ; v1(35.052,10.033) 36.919,11.9 v1(36.919,14.262)
AH: U1.17 U2.29 | length 14.4
  Top Layer w0.254: v1@19.707,21.463 21.293,23.049 U2.29@21.316,23.049
  SIGNAL w0.254: v1(19.685,21.463) 21.195,21.463 21.84,20.818 21.84,14.474 20.468,13.102 v1(20.468,12.734)
  Bottom Layer w0.254: v1(20.468,12.734) 20.492,12.71 U1.17@20.492,11.708
AL: U1.18 U2.17 | length 5.9
  Top Layer w0.254: U2.17@20.255,17.038 20.291,17.038 20.84,16.489 20.903,16.489 21.188,16.204 21.188,15.8 20.993,15.605 v1(20.993,12.734)
  Bottom Layer w0.254: v1(20.993,12.734) 21.004,12.723 U1.18@21.004,11.695
BH: U1.19 U2.30 | length 14.6
  Top Layer w0.254: v1@19.622,22.098 20.926,23.402 U2.30@20.962,23.402
  SIGNAL w0.254: v1(19.558,22.098) 21.075,22.098 22.204,20.969 22.204,14.323 21.518,13.637 v1(21.518,12.734)
  Bottom Layer w0.254: U1.19@21.516,11.684 21.517,12.733 v1(21.518,12.734)
BL: U1.20 U2.18 | length 6.3
  Top Layer w0.254: U2.18@20.608,17.392 22.043,15.957 v1(22.043,12.734)
  Bottom Layer w0.254: U1.20@22.029,11.698 22.029,12.721 v1(22.043,12.734)
CH: U1.21 U2.31 | length 14.8
  Top Layer w0.254: v1@19.478,22.78 19.633,22.78 U2.31@20.608,23.756
  SIGNAL w0.254: v1(19.431,22.733) 20.955,22.733 22.568,21.12 v1(22.568,12.734)
  Bottom Layer w0.254: U1.21@22.541,11.709 22.541,12.708 v1(22.568,12.734)
CL: U1.22 U2.19 | length 6.9
  Top Layer w0.254: U2.19@20.962,17.746 23.008,15.7 23.008,14.275 23.093,14.19 v1(23.093,12.734)
  Bottom Layer w0.254: U1.22@23.041,11.709 23.041,12.616 23.093,12.668 v1(23.093,12.734)
DC_CAL: U1.12 U2.43 | length 13.1
  Top Layer w0.254: U2.43@14.598,23.402 17.989,20.012 v1(17.989,12.734)
  Bottom Layer w0.254: v1@18.002,12.721 18.002,12.288 18.016,12.274 U1.12@18.016,11.684
DCBUS: C3.1 C4.1 C17.2 C37.2 C40.1 C41.1 C42.1 C43.1 C44.1 C45.1 C46.1 C47.1 D4.2 D?.2 Q1.D Q2.D Q3.D R32.2 U1.29 U1.53 U1.54 U5.7 | length 109.7
  Top Layer w0.55: D?.2@24.37,1.905 D?.2@24.955,2.49 ; C46.1@24.384,8.179 C46.1@24.688,7.874 ; v1(30.353,6.231) 31.04,6.917 31.831,6.917 32.279,7.366 33.892,7.366 ; U5.7@33.063,8.82 33.063,8.195 33.892,7.366 ; C37.2@39.116,8.471 R32.2@37.592,8.471 36.487,7.366 33.892,7.366
  SIGNAL w1: v1(0.762,7.62) v1(0.762,7.112) v1(0.762,6.604) v1(0.762,6.096) v1(0.762,5.588) v1(0.762,5.08) v1(0.762,4.572) 0.762,3.977 2.081,2.658 13.299,2.658 15.449,0.508 24.541,0.508 28.431,4.398
  Bottom Layer w0.254: 1.016,6.858 2,7.842 3.143,7.842 3.997,8.696 C4.1@4.399,8.696 ; C4.1@4.399,8.823 C3.1@4.399,10.407 ; 13.244,2.513 13.516,2.785 ; v1(30.353,6.231) 30.526,6.231 32.131,7.836 C17.2@32.131,7.963
  Bottom Layer w0.55: C41.1@28.067,3.751 28.389,3.429 C40.1@30.226,3.429
  Bottom Layer w1: 3.287,19.798 0.664,17.175 0.664,7.718 v1(0.762,7.62) v1(0.762,7.112) v1(0.762,6.604) v1(0.762,6.096) v1(0.762,5.588) v1(0.762,5.08) v1(0.762,4.572) 0.762,3.977 0.762,3.976 1.69,3.048 3.638,3.048 4.399,3.809 4.399,4.666 4.898,5.164 10.463,5.164 11.049,4.579 11.049,3.175 11.711,2.513 13.244,2.513 ; 5.389,17.797 5.969,17.216 10.865,17.216 13.313,19.664 ; 15.693,17.653 15.922,17.424 21.233,17.424 23.24,19.431 24.13,19.431
  other v1: 28.448,3.302 29.083,3.302 29.718,3.302 30.353,3.302 26.67,3.429 29.718,3.85 30.353,3.85 26.67,4.064 29.718,4.445 30.353,4.445 26.67,4.699 29.718,5.008 30.353,5.008 26.67,5.334 25.908,5.349 28.448,5.588 29.718,5.588 27.813,5.602 29.083,5.602 30.353,5.602 25.908,5.969 26.67,5.969 27.813,6.223 28.448,6.223 29.083,6.223 29.718,6.223 25.908,6.591 26.67,6.604
DCIN: D?.1 pad.@33.274,3.683 | length 4.5
  Top Layer w1: D?.1@28.97,1.905 D?.1@28.984,1.919 ; pad.@32.293,1.919 pad.@33.101,2.727
  Top Layer w1.7: D?.1@28.984,1.919 pad.@32.293,1.919
EN_GATE: U1.16 U2.40 | length 17.4
  Top Layer w0.254: U2.40@15.659,24.463 19.675,20.447 v1@19.752,20.447
  SIGNAL w0.254: v1(19.818,20.447) 20.47,21.099 21.045,21.099 21.372,20.771 21.372,14.739 19.99,13.357 19.99,12.848 19.943,12.801 v1(19.943,12.734)
  Bottom Layer w0.254: v1(19.943,12.734) 19.943,12.668 19.99,12.62 19.99,11.709 U1.16@20.016,11.684
ENCA: MOTOR.1 R7.2 U2.16 | length 33.2
  Top Layer w0.254: U2.16@19.901,16.685 19.901,16.68 v1@20.574,16.007 ; v1(20.587,20.447) 22.707,20.447 25.109,22.849 25.109,25.25 23.943,26.416 v1(20.955,26.416) ; MOTOR.1@27.051,33.528 MOTOR.1@27.132,33.528
  Top Layer w0.5: R7.2@26.67,29.756 27.132,30.218 MOTOR.1@27.132,33.528
  SIGNAL w0.254: v1(20.587,20.447) 20.701,20.333 v1(20.701,16.002) ; v1(20.955,26.416) 20.955,26.483 20.587,26.851 20.587,28.969 24.003,32.385 25.989,32.385 MOTOR.1@27.132,33.528
ENCB: MOTOR.2 R6.2 U2.41 | length 42.3
  Top Layer w0.254: U2.41@15.305,24.11 16.693,22.722 v1(16.693,21.971)
  Top Layer w0.5: R6.2@25.005,29.91 MOTOR.2@25.005,33.528
  SIGNAL w0.254: v1(10.79,31.635) 10.79,37.714 11.303,38.227 20.433,38.227 MOTOR.2@25.132,33.528 ; v1(12.099,24.346) 14.318,24.346 v1(16.693,21.971)
  Bottom Layer w0.254: v1(10.79,31.635) 10.78,31.625 10.78,26.616 12.099,25.297 v1(12.099,24.346)
ENCZ: MOTOR.3 R5.2 U2.15 | length 23.2
  Top Layer w0.254: v1(19.171,18.288) 19.131,18.249 19.131,18.086 18.947,17.902 18.947,16.969 19.548,16.367 U2.15@19.548,16.331
  Top Layer w0.5: R5.2@23.259,29.91 MOTOR.3@23.259,33.528
  SIGNAL w0.254: v1(19.171,18.288) 19.171,18.348 18.744,18.775 18.74,18.775 18.74,22.731 19.812,23.803 19.812,30.208 MOTOR.3@23.132,33.528
GH_A: R11.2 U1.47 | length 25.2
  SIGNAL w0.254: v1(1.524,11.049) 1.524,11.149 1.528,11.153 1.528,8.926 2.227,8.227 2.227,4.882 2.376,4.733 13.929,4.733 15.974,2.688 16.764,2.688 17.019,2.943 17.019,3.078 v1(17.066,3.125)
  Bottom Layer w0.254: v1(1.524,11.049) 1.571,11.096 1.571,11.252 2.437,12.118 R11.2@2.545,12.118 ; U1.47@17.041,4.115 17.041,3.15 v1(17.066,3.125)
GH_B: R12.2 U1.42 | length 17
  SIGNAL w0.254: v1(7.225,12.118) 8.329,12.118 15.858,4.589 18.104,4.589 19.501,3.192 v1(19.516,3.192)
  Bottom Layer w0.254: R12.2@7.117,12.118 v1(7.225,12.118) ; v1(19.516,3.192) U1.42@19.516,4.14
GH_C: R13.2 U1.37 | length 33.2
  SIGNAL w0.254: v1(1.805,13.246) 1.037,12.478 1.037,8.902 1.863,8.076 1.863,4.614 2.718,3.759 14.388,3.759 16.348,1.799 20.776,1.799 21.372,2.396 21.372,2.531 v1(22.016,3.175)
  Bottom Layer w0.254: v1@1.855,13.246 2.437,13.828 R13.2@2.545,13.828 ; v1(22.016,3.175) U1.37@22.016,4.14
GL_A: R17.2 U1.45 | length 28.9
  SIGNAL w0.254: v1(7.862,14.859) 6.74,15.981 4.992,15.981 4.318,15.307 4.318,8.636 6.096,6.858 13.061,6.858 15.728,4.191 16.973,4.191 v1(17.989,3.175)
  Bottom Layer w0.254: R17.2@7.117,15.539 7.225,15.539 7.862,14.902 v1(7.862,14.859) ; v1(17.989,3.175) 17.991,3.177 17.991,4.115 U1.45@18.016,4.14
GL_B: R18.2 U1.40 | length 18.8
  SIGNAL w0.254: v1(7.862,13.246) 16.156,4.953 18.74,4.953 v1(20.516,3.177)
  Bottom Layer w0.254: R18.2@7.117,13.828 7.225,13.828 7.807,13.246 v1(7.862,13.246) ; v1(20.516,3.177) U1.40@20.516,4.14
GL_C: R19.2 U1.35 | length 37.1
  SIGNAL w0.254: v1(1.651,14.224) 1.628,14.201 1.02,14.201 0.673,13.854 0.673,8.751 1.499,7.925 1.499,4.463 2.567,3.395 14.238,3.395 16.198,1.435 21.066,1.435 22.784,3.153 v1(22.926,3.153)
  Bottom Layer w0.254: v1@1.674,14.247 1.674,14.776 2.437,15.539 R19.2@2.545,15.539 R19.2@2.653,15.539 ; v1(22.926,3.153) 23.016,3.243 U1.35@23.016,4.14
GND: C1.2 C2.2 C3.2 C4.2 C5.2 C6.1 C10.2 C13.1 C14.1 C15.2 C16.1 C17.1 C18.2 C19.2 C20.2 C21.1 C22.2 C23.1 C24.1 C25.1 C26.1 C27.1 C28.1 C29.2 C30.2 C31.2 C33.1 C37.1 C38.2 C40.2 C41.2 C42.2 C43.2 C44.2 C45.2 C46.2 C47.2 D1.1 D2.1 D4.1 E1.2 I2C.4 MOTOR.4 pad.@37.211,3.683 Q4.S R4.2 R9.1 R14.2 R15.1 R22.1 R23.1 R29.1 R31.2 R35.2 R36.1 R37.1 R38.2 SW1.1 SW2.1 SWD.4 U1.8 U1.28 U1.30 U1.32 U1.44 U1.57 U2.8 U2.23 U2.47 U3.2 U5.5 UART.4 | length 3.4
  Top Layer w0.254: C26.1@9.652,23.914 C26.1@9.669,23.897 ; C28.1@11.159,23.897 C28.1@11.176,23.914 ; v1@14.765,16.325 14.765,16.463 15.305,17.003 U2.8@15.305,17.038
  Bottom Layer w0.203: U1.44@18.567,4.089 18.567,3.295 19.131,2.731 v1@19.932,2.731
  other v1: 20.016,2.814 14.718,16.278 12.553,17.145 5.743,37.997 7.239,37.997 9.144,38.004
I2C_SCL: I2C.3 U2.21 | length 31.7
  Top Layer w0.254: I2C.3@5.097,7.009 I2C.3@5.497,7.009 ; I2C.3@6.209,7.124 I2C.3@6.221,7.112 ; I2C.3@6.987,6.936 8.306,8.255 8.306,10.617 7.747,11.176 6.985,11.176 6.519,11.642 6.519,12.827 9.231,15.539 v1(10.414,15.539) ; v1(20.193,19.05) 21.077,19.05 U2.21@21.669,18.458
  SIGNAL w0.254: v1(10.414,15.539) 11.733,15.539 12.099,15.174 12.099,13.604 13.511,12.192 16.654,12.192 20.193,15.731 v1(20.193,19.05)
I2C_SDA: I2C.2 U2.22 | length 32
  Top Layer w0.254: I2C.2@7.059,8.624 7.942,9.507 7.942,10.466 7.596,10.812 6.664,10.812 6.155,11.321 6.155,14.337 7.947,16.129 v1(10.973,16.129) ; v1(19.685,19.685) 19.732,19.638 21.191,19.638 U2.22@22.023,18.806
  SIGNAL w0.254: v1(10.973,16.129) 11.079,16.023 11.764,16.023 12.463,15.324 12.463,13.754 13.661,12.556 16.503,12.556 19.685,15.738 v1(19.685,19.685)
M_A: C8.1 MOTOR.8 pad.MotorPad_U Q1.S Q4.D U1.46 | length 36.9
  SIGNAL w0.254: v1(5.842,16.383) 7.15,17.691 7.15,19.197 v1(6.731,19.616)
  Bottom Layer w0.254: Q4.D@1.904,26.543 2.128,26.543 4.175,24.496 5.223,24.496 7.126,22.593 7.126,22.479 Q1.S@7.38,22.225 ; v1@5.886,16.383 5.886,12.42 5.588,12.122 5.588,8.379 6.191,7.776 7.551,7.776 8.087,7.239 8.717,7.239 C8.1@8.971,6.985 13.672,6.985 15.543,5.114 17.366,5.114 17.491,4.989 U1.46@17.491,4.166 ; v1(6.731,19.616) 7.425,19.616 Q1.S@7.494,19.685 Q1.S@7.494,20.955 Q1.S@7.494,22.225
M_B: C9.1 MOTOR.7 pad.MotorPad_V Q2.S Q5.D U1.41 | length 36.6
  Top Layer w0.254: v1(13.716,8.025) 13.716,9.702 15.422,11.408 15.422,14.055 15.678,14.312 v1(15.678,15.022)
  SIGNAL w0.254: v1@15.725,15.069 15.725,17.308 17.272,18.854 v1(17.272,20.012)
  Bottom Layer w0.254: C9.1@8.971,8.636 13.105,8.636 v1(13.716,8.025) 15.899,5.842 19.183,5.842 19.99,5.035 U1.41@19.99,4.166 ; Q5.D@12.064,26.543 12.208,26.399 12.432,26.399 14.392,24.439 15.326,24.439 Q2.S@17.54,22.225 ; Q2.S@17.654,19.685 Q2.S@17.654,20.955 Q2.S@17.654,22.225
M_B_Current: Q5.S R20.1 R22.2 U1.39 | length 25.4
  SIGNAL w0.254: v1(21.209,5.556) 21.876,6.223 22.726,6.223 27.534,11.031 27.534,17.501 v1(30.734,20.701)
  Bottom Layer w0.254: U1.39@21.016,4.14 21.016,5.297 v1@21.209,5.49
  Bottom Layer w0.381: v1(30.734,20.701) 30.734,20.847 31.477,21.59 R20.1@31.585,21.59 R22.2@31.585,24.625
M_C: C12.1 MOTOR.6 pad.MotorPad_W Q3.S Q6.D U1.36 | length 19.8
  Top Layer w0.254: v1(27.814,19.685) 27.814,15.792 v1(28.874,14.732)
  SIGNAL w0.254: v1@23.368,5.583 28.874,11.088 v1(28.874,14.732)
  Bottom Layer w0.254: U1.36@22.541,4.166 22.541,4.884 22.807,5.15 22.895,5.15 23.301,5.556 v1(23.368,5.556) ; v1(28.874,14.732) 29.464,14.732 29.807,14.389 C12.1@29.807,14.262
  other v1: 27.051,19.685 27.051,20.955 27.814,20.955 27.051,22.225 27.814,22.225 24.13,28.81 25.15,28.81 25.752,28.81 26.289,28.81 24.638,28.829 24.13,29.326 25.752,29.326 24.13,29.845 25.744,29.845 25.744,30.353 24.13,30.391 24.13,30.861 25.744,30.861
